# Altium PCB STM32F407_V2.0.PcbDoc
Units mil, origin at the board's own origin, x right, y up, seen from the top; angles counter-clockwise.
Board outline 4845 x 5210 mil, 2 copper layers (Top Layer, Bottom Layer); 115 components, 85 nets, 494 pads, 265 vias.
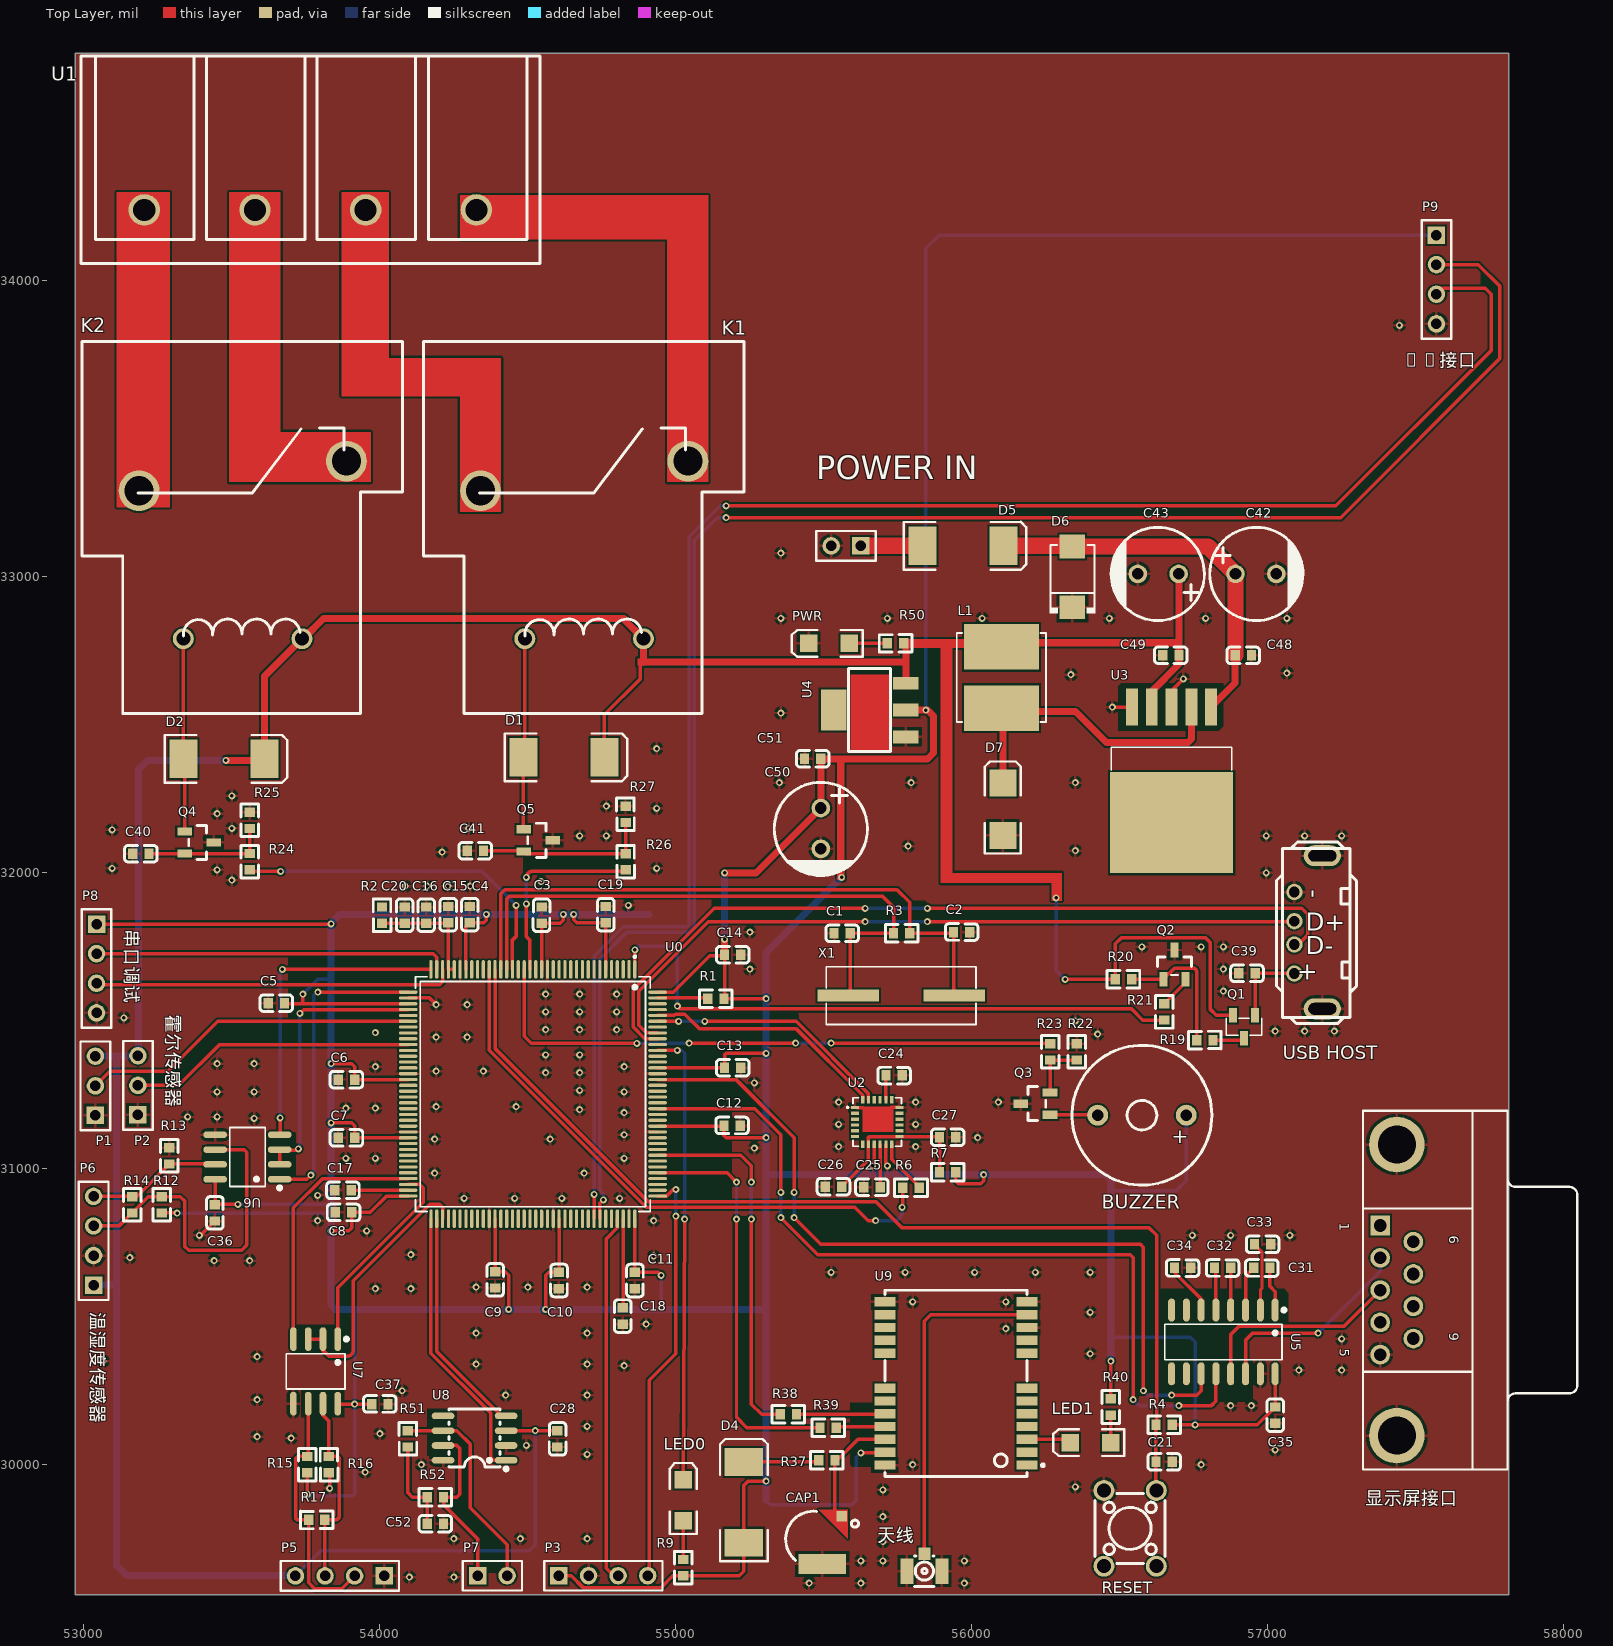
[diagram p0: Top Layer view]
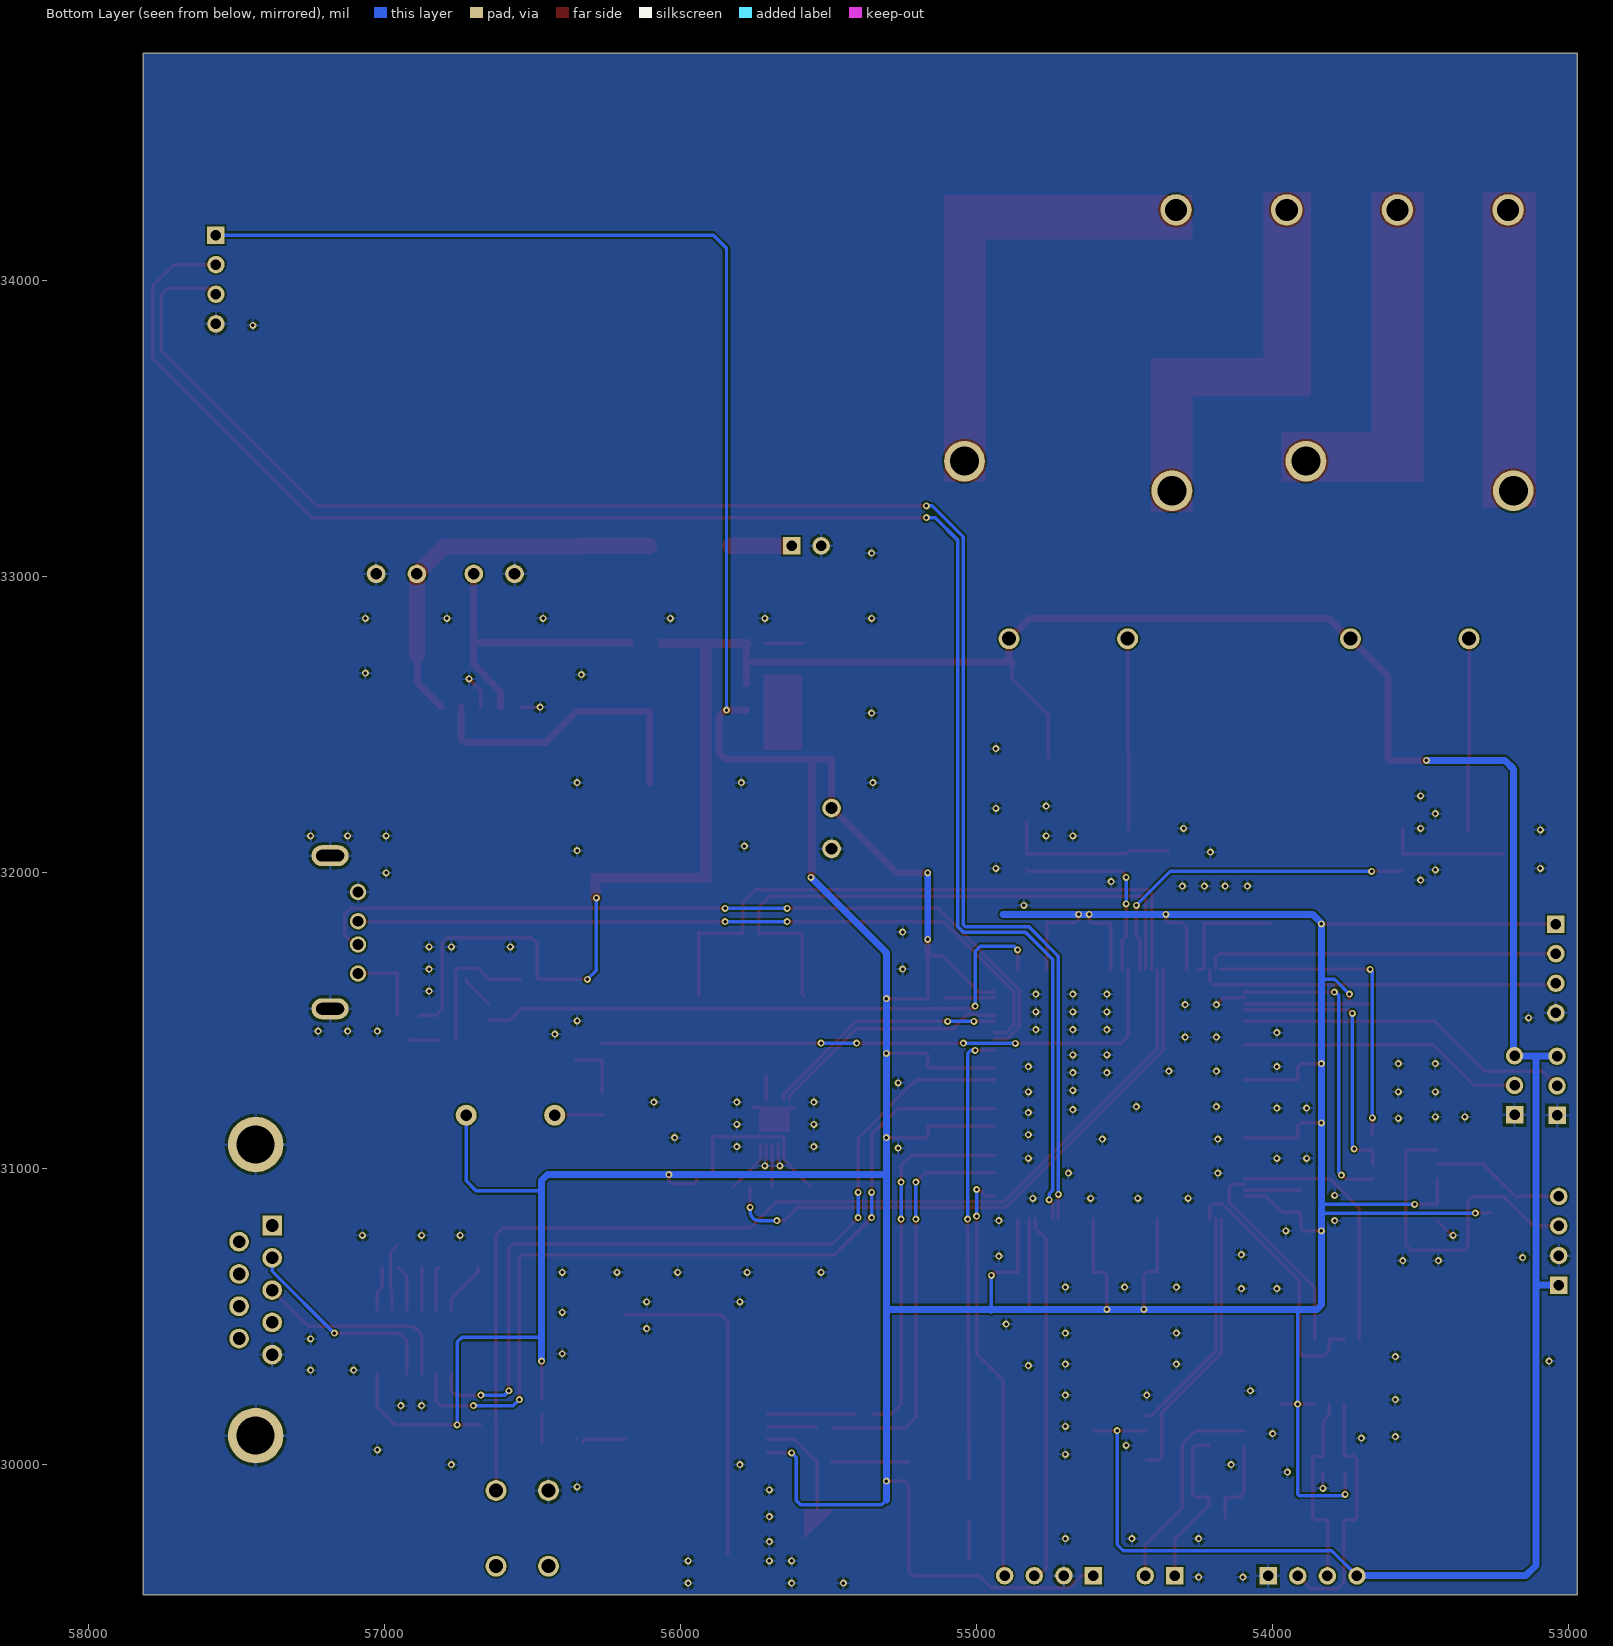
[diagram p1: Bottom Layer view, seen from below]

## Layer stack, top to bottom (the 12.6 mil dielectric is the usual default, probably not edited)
Top Solder: solder mask 0.4, Solder Resist, Dk 3.5
Top Layer: signal copper 1.4
Dielectric 1: dielectric 12.6, FR-4, Dk 4.8
Bottom Layer: signal copper 1.4
Bottom Solder: solder mask 0.4, Solder Resist, Dk 3.5

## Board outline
52970,29560 52970,34770 57815,34770 57815,29560

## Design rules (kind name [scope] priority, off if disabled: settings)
Clearance [All] p1: gap=6
PolygonConnect [All] p1: connectstyle=Relief reliefconductorwidth=10 reliefentries=4 polygonreliefangle="90 Angle" airgapwidth=10
RoutingVias [All] p1: holewidth=11.81 width=23.62 viastyle="Through Hole" minholewidth=11.81 minwidth=23.62 maxholewidth=11.81 maxwidth=23.62
SilkToSolderMaskClearance [IsPad] p1: minsilkscreentomaskgap=0.5 clearancetoexposedcopper=TRUE
SolderMaskExpansion [All] p1: expansion=4
Width [All] p1: maxlimit=78.74 minlimit=9.84 preferedwidth=11.81
Width PWR [InNetClass('PWR')] p2: maxlimit=78.74 minlimit=10 preferedwidth=23.62
29 further rules are at their usual default settings.

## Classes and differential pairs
net class PWR: GND "POWER IN" VCC3.3 VCC5
net class GND: GND

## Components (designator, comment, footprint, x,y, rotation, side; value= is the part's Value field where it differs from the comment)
BUZZER "TMB12A03" BUZ-TH_BD12.0-P7.60-D0.6-FD 56575.1,31181.03 r180 top (schematic designator BUZZER1)
C1 "22nF" SMD_CAP_0603 55562.29,31795.71 r180 top
C2 "22nF" SMD_CAP_0603 55965.83,31799.65 r0 top
C3 "100nF" SMD_CAP_0603 54546.54,31856.73 r90 top
C4 "100nF" SMD_CAP_0603 54304.41,31858.7 r90 top
C5 "100nF" SMD_CAP_0603 53650,31560 r180 top
C6 "100nF" SMD_CAP_0603 53887.08,31301.61 r180 top
C7 "100nF" SMD_CAP_0603 53887.09,31104.76 r180 top
C8 "100nF" SMD_CAP_0603 53877.24,30852.8 r180 top
C9 "100nF" SMD_CAP_0603 54389.06,30624.45 r270 top
C10 "100nF" SMD_CAP_0603 54605,30622.44 r270 top
C11 "100nF" SMD_CAP_0603 54861.5,30622.48 r270 top
C12 "100nF" SMD_CAP_0603 55190.24,31146.1 r0 top
C13 "100nF" SMD_CAP_0603 55192.21,31340.98 r0 top
C14 "100nF" SMD_CAP_0603 55192.21,31722.87 r0 top
C15 "10uF" SMD_CAP_0603 54231.57,31858.7 r90 top
C16 "100nF" SMD_CAP_0603 54156.77,31856.73 r90 top
C17 "225nF" SMD_CAP_0603 53875.28,30927.6 r180 top
C18 "225nF" SMD_CAP_0603 54820.16,30502.4 r270 top
C19 "100nF" SMD_CAP_0603 54763.07,31858.7 r270 top
C20 "225nF" SMD_CAP_0603 54083.94,31856.73 r90 top
C21 "100nF" SMD_CAP_0603 56650,30010 r180 top
C24 "10uF" SMD_CAP_0603 55737.48,31315.39 r180 top
C25 "100nF" SMD_CAP_0603 55662.68,30937.44 r0 top
C26 "10uF" SMD_CAP_0603 55532.76,30939.41 r0 top
C27 "100nF" SMD_CAP_0603 55918.58,31106.73 r180 top
C28 "100nF" SMD_CAP_0603 54600,30087.44 r270 top
C31 "100nF" SMD_CAP_0603 56980,30665 r180 top
C32 "100nF" SMD_CAP_0603 56847.44,30665 r180 top
C33 "100nF" SMD_CAP_0603 56982.56,30745 r180 top
C34 "100nF" SMD_CAP_0603 56712.33,30665 r180 top
C35 "100nF" SMD_CAP_0603 57025,30167.44 r270 top
C36 "100nF/50V" SMD_CAP_0603 53442.2,30850.83 r270 top
C37 "100nF/50V" SMD_CAP_0603 54000,30205 r0 top
C39 "100nF" SMD_CAP_0603 56930,31660 r0 top
C40 "100nF" SMD_CAP_0603 53192.44,32065 r180 top
C41 "100nF" SMD_CAP_0603 54322.44,32075 r180 top
C42 "680uF" CAP-TH_BD8.0-P3.50-D1.0-FD 56960,33010 r0 top
C43 "220uF" CAP-TH_BD8.0-P3.50-D1.0-FD 56630,33010 r180 top
C48 "100nF" SMD_CAP_0603 56917.44,32735 r180 top
C49 "100nF" SMD_CAP_0603 56672.44,32735 r0 top
C50 "220uF" CAP-TH_BD8.0-P3.50-D1.0-FD 55490,32150 r270 top
C51 "100nF" SMD_CAP_0603 55462.44,32385 r0 top
C52 "10nF/50V/10%" SMD_CAP_0603 54187.44,29800 r0 top
CAP1 "70mF" CAP-TH_XH414HG 55555.88,29765.83 r0 top
D1 "Diode" SMC 54621.81,32390 r0 top
D2 "Diode" SMC 53473.19,32385 r0 top
D4 "Diode" SMC 55230,29873.19 r90 top
D5 "Diode" SMC 55970,33105 r0 top
D6 "SMBJ8.0A" SMB_L4.6-W3.6-LS5.3-RD 56340,33000 r90 top
D7 "SK54" SMB 56105,32215 r90 top
K1 "HF105F-1/012D-1HS" RELAY-TH_HF105F-XXX-1HXXX-XXX 54690.39,33090.98 r0 top
K2 "HF105F-1/012D-1HS" RELAY-TH_HF105F-XXX-1HXXX-XXX 53536.69,33090.98 r0 top
L1 "33uH" IND-SMD_L7.0-W6.8 56100,32660 r270 top
LED0 "LED0" 3.2X1.6X1.1 55025,29880 r90 top (schematic designator DS1)
LED1 "LED0" 3.2X1.6X1.1 56401.1,30075 r180 top (schematic designator DS2)
P1 "Hall1" HDR1X3 53038.66,31180.35 r90 top
P2 "Hall2" HDR1X3 53182.36,31181.93 r90 top
P3 "Header 4" HDR1X4 54605,29625 r0 top
P5 "Header 4" HDR1X4 54014.65,29624.45 r180 top
P6 "Header 4" HDR1X4 53032.76,30606.73 r90 top
P7 "Header 2" HDR1X2 54330,29625 r0 top
P8 "Header 4" HDR1X4 53042.6,31826.81 r270 top
P9 "Header 4" HDR1X4 57570,34155 r270 top
"POWER IN" "Header 2" HDR1X2 55625,33105 r180 top (schematic designator P4)
PWR "LED2" 3.2X1.6X1.1 55517.44,32775 r180 top (schematic designator DS3)
Q1 "SI2301" SOT-23-3_L2.9-W1.3-P1.90-LS2.4-BR 56920,31480 r90 top
Q2 "S8050" NUP2105LT1G 56685,31690 r0 top
Q3 "S8050" NUP2105LT1G 56215,31220 r90 top
Q4 "S8050" NUP2105LT1G 53389.2,32102.6 r270 top
Q5 "S8050" NUP2105LT1G 54535,32110 r270 top
R1 "0R" SMD_RES_0603 55135,31575 r180 top
R2 "10R" SMD_RES_0603 54007.17,31856.73 r270 top
R3 "1M" SMD_RES_0603 55763.07,31795.71 r180 top
R4 "10k" SMD_RES_0603 56650,30135 r0 top
R6 "1k" SMD_RES_0603 55794.57,30935.47 r180 top
R7 "10R" SMD_RES_0603 55918.58,30988.62 r180 top
R9 "510R" SMD_RES_0603 55025,29652.44 r270 top
R12 "360R" SMD_RES_0603 53263.07,30878.38 r90 top
R13 "360R" SMD_RES_0603 53288.66,31043.74 r90 top
R14 "120R" SMD_RES_0603 53162.68,30878.38 r270 top
R15 "360R" SMD_RES_0603 53755.2,30000.43 r90 top
R16 "360R" SMD_RES_0603 53828.03,30000.43 r270 top
R17 "120R" SMD_RES_0603 53786.69,29813.43 r180 top
R19 "10k" SMD_RES_0603 56787.44,31435 r0 top
R20 "100k" SMD_RES_0603 56512.44,31640 r180 top
R21 "4.7K" SMD_RES_0603 56650,31530 r270 top
R22 "10K" SMD_RES_0603 56355,31395 r90 top
R23 "1K" SMD_RES_0603 56265,31395 r270 top
R24 "4.7K" SMD_RES_0603 53560,32037.56 r270 top
R25 "47K" SMD_RES_0603 53560,32177.44 r90 top
R26 "4.7K" SMD_RES_0603 54830,32037.44 r270 top
R27 "47K" SMD_RES_0603 54830,32197.44 r90 top
R37 "120R" SMD_RES_0603 55510,30015 r180 top
R38 "510R" SMD_RES_0603 55380,30170 r0 top
R39 "510R" SMD_RES_0603 55515,30125 r0 top
R40 "510R" SMD_RES_0603 56470,30195 r90 top
R50 "2K" SMD_RES_0603 55742.44,32775 r0 top
R51 "60.4R/5%/1/8W" SMD_RES_0603 54095,30087.44 r90 top
R52 "60.4R/5%/1/8W" SMD_RES_0603 54187.44,29890 r0 top
RESET "SW" SW-TH_4P-L6.0-W6.0-P4.50-LS6.5 56535,29785 r270 top (schematic designator SW1)
U0 "STM32F407ZGT6" LQFP-144_L20.0-W20.0-P0.50-LS22.0-BL 54517.01,31252.4 r180 top locked
U1 "DBT50B-9.5-4P" CONN-TH_DBT50B-9.5-4P 53765,34240 r180 top
U2 "MPU6050" QFN-24_L4.0-W4.0-P0.50-BL-EP2.6 55680.39,31157.91 r270 top
U3 "LM2596R-5.0" TO-263-5_L10.2-W8.6-P1.70-LS14.4-TL 56675,32365 r270 top
U4 "AMS1117" SOT-223_L6.7-W3.5-P2.30-BR 55655,32550 r0 top
U5 "MAX3232ID" SOIC-16_L9.9-W3.9-P1.27-LS6.0-BL 56850,30415 r180 top
U6 "SP3485EEN" SOP-8_L5.0-W4.0-P1.27-LS6.0-BL 53552.44,31039.8 r90 top
U7 "SP3485EEN" SOP-8_L5.0-W4.0-P1.27-LS6.0-BL 53782.76,30315.39 r180 top
U8 "TJA1050T/CM,118" SOIC-8_L5.0-W4.0-P1.27-LS6.0-BL 54320,30090 r90 top
U9 "KH-1612-UB8X" GPSM-SMD_KH-1612-UBXX 55946.46,30274.61 r0 top
"USB HOST" "C16722" USB-A-TH_4P-V-F_13.7MM 57137.24,31799.3 r180 top
X1 "8MHz" HC-49S_L11.4-W4.8 55761.1,31585.08 r180 top
天线 "KH-IPEX-K501-29" ANT-SMD_KH-IPEX-K501-29 55840,29670 r0 top (schematic designator RF1)
显示屏接口 "D Connector 9" DSUB1.385-2H9 57810,30590 r270 top (schematic designator J1)

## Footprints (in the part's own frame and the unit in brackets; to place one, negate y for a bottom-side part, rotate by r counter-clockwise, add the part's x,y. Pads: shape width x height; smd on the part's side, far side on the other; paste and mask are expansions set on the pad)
3.2X1.6X1.1 [mm] "SMT LED; 2 Flat Leads"
  rect 1.5x1.5 smd: 1(-1.75,0) 2(1.75,0)
  silkscreen extent -2.9,-1.15 3.2,1.15
ANT-SMD_KH-IPEX-K501-29 [mm]
  rect 1.1x2.2 smd: 1(-1.5,-0.75) 3(1.5,-0.75)
  rect 1x1.05 smd: 2(0,0.75)
  silkscreen extent -0.84,-2.05 0.84,0.55
BUZ-TH_BD12.0-P7.60-D0.6-FD [mm]
  round 1.8 hole 1: 1(-3.8,0) 2(3.8,0)
  silkscreen extent -6,-6 6,6
CAP-TH_BD8.0-P3.50-D1.0-FD [mm]
  round 1.6 hole 1: 1(-1.75,0) 2(1.75,0)
  silkscreen extent -3.96,-4 4.04,4
CAP-TH_XH414HG [mil]
  round 0 smd: 1(-23.48,57.63)
  rect 35x35 smd: 1(5,60)
  rect 161.4x66.93 smd: 2(-60.88,-100.83)
  Top Layer region: -72.69,82.24 25.74,82.24 25.74,-16.19
  silkscreen extent -185,-89 61,77
CONN-TH_DBT50B-9.5-4P [mm]
  round 2.7 hole 1.9: 1(-14.25,0) 2(-4.75,0) 3(4.75,0) 4(14.25,0)
  silkscreen extent -19.7,-13.21 19.7,4.6
DSUB1.385-2H9 [mm] "Connector; D Subminiature; 9 Position; Right Angle; Pitch 1.385 mm"
  rect 1.69x1.69 hole 1.09: 1(-5.54,-10.92)
  round 1.69 hole 1.09: 2(-2.77,-10.92) 3(0,-10.92) 4(2.77,-10.92) 5(5.54,-10.92) 6(-4.155,-8.08) 7(-1.385,-8.08) 8(1.385,-8.08) 9(4.155,-8.08)
  round 4.76 hole 3.26: 10(-12.495,-9.5) 11(12.495,-9.5)
  silkscreen extent -15.4,-12.4 15.4,6
GPSM-SMD_KH-1612-UBXX [mm]
  rect 1.8x0.8 smd: 1(6.1,-7) 2(6.1,-5.9) 3(6.1,-4.8) 4(6.1,-3.7) 5(6.1,-2.6) 6(6.1,-1.5) 7(6.1,-0.4) 8(6.1,2.6) 9(6.1,3.7) 10(6.1,4.8) 11(6.1,5.9) 12(6.1,7) 13(-6.1,7) 14(-6.1,5.9) 15(-6.1,4.8) 16(-6.1,3.7) 17(-6.1,2.6) 18(-6.1,-0.4) 19(-6.1,-1.5) 20(-6.1,-2.6) 21(-6.1,-3.7) 22(-6.1,-4.8) 23(-6.1,-5.9) 24(-6.1,-7)
  silkscreen extent -6.1,-8 7.58,8
HC-49S_L11.4-W4.8 [mm] "晶振8M"
  rect 5.274x1.02 smd: 1(4.553,0) 2(-4.553,0)
  silkscreen extent -6.43,-2.48 6.43,2.48
HDR1X2 [mm] "Connector; Header; 2 Position"
  rect 1.5x1.5 hole 0.9: 1(0,0)
  round 1.5 hole 0.9: 2(2.54,0)
  silkscreen extent -1.27,-1.27 3.81,1.27
HDR1X3 [mm] "Connector; Header; 3 Position"
  rect 1.5x1.5 hole 0.9: 1(0,0)
  round 1.5 hole 0.9: 2(2.54,0) 3(5.08,0)
  silkscreen extent -1.27,-1.27 6.35,1.27
HDR1X4 [mm] "Connector; Header; 4 Position"
  rect 1.5x1.5 hole 0.9: 1(0,0)
  round 1.5 hole 0.9: 2(2.54,0) 3(5.08,0) 4(7.62,0)
  silkscreen extent -1.27,-1.27 8.89,1.27
IND-SMD_L7.0-W6.8 [mm]
  rect 3.924x6.42 smd: 1(2.628,0) 2(-2.628,0)
  silkscreen extent -3.83,-3.83 3.83,3.83
LQFP-144_L20.0-W20.0-P0.50-LS22.0-BL [mm] "MCU"
  oval 0.28x1.6 smd: 1(-8.75,-10.7) 2(-8.25,-10.7) 3(-7.75,-10.7) 4(-7.25,-10.7) 5(-6.75,-10.7) 6(-6.25,-10.7) 7(-5.75,-10.7) 8(-5.25,-10.7) 9(-4.75,-10.7) 10(-4.25,-10.7) 11(-3.75,-10.7) 12(-3.25,-10.7) 13(-2.75,-10.7) 14(-2.25,-10.7) 15(-1.75,-10.7) 16(-1.25,-10.7) 17(-0.75,-10.7) 18(-0.25,-10.7) 19(0.25,-10.7) 20(0.75,-10.7) 21(1.25,-10.7) 22(1.75,-10.7) 23(2.25,-10.7) 24(2.75,-10.7) 25(3.25,-10.7) 26(3.75,-10.7) 27(4.25,-10.7) 28(4.75,-10.7) 29(5.25,-10.7) 30(5.75,-10.7) 31(6.25,-10.7) 32(6.75,-10.7) 33(7.25,-10.7) 34(7.75,-10.7) 35(8.25,-10.7) 36(8.75,-10.7) 73(8.75,10.7) 74(8.25,10.7) 75(7.75,10.7) 76(7.25,10.7) 77(6.75,10.7) 78(6.25,10.7) 79(5.75,10.7) 80(5.25,10.7) 81(4.75,10.7) 82(4.25,10.7) 83(3.75,10.7) 84(3.25,10.7) 85(2.75,10.7) 86(2.25,10.7) 87(1.75,10.7) 88(1.25,10.7) 89(0.75,10.7) 90(0.25,10.7) 91(-0.25,10.7) 92(-0.75,10.7) 93(-1.25,10.7) 94(-1.75,10.7) 95(-2.25,10.7) 96(-2.75,10.7) 97(-3.25,10.7) 98(-3.75,10.7) 99(-4.25,10.7) 100(-4.75,10.7) 101(-5.25,10.7) 102(-5.75,10.7) 103(-6.25,10.7) 104(-6.75,10.7) 105(-7.25,10.7) 106(-7.75,10.7) 107(-8.25,10.7) 108(-8.75,10.7)
  oval 1.6x0.28 smd: 37(10.7,-8.75) 38(10.7,-8.25) 39(10.7,-7.75) 40(10.7,-7.25) 41(10.7,-6.75) 42(10.7,-6.25) 43(10.7,-5.75) 44(10.7,-5.25) 45(10.7,-4.75) 46(10.7,-4.25) 47(10.7,-3.75) 48(10.7,-3.25) 49(10.7,-2.75) 50(10.7,-2.25) 51(10.7,-1.75) 52(10.7,-1.25) 53(10.7,-0.75) 54(10.7,-0.25) 55(10.7,0.25) 56(10.7,0.75) 57(10.7,1.25) 58(10.7,1.75) 59(10.7,2.25) 60(10.7,2.75) 61(10.7,3.25) 62(10.7,3.75) 63(10.7,4.25) 64(10.7,4.75) 65(10.7,5.25) 66(10.7,5.75) 67(10.7,6.25) 68(10.7,6.75) 69(10.7,7.25) 70(10.7,7.75) 71(10.7,8.25) 72(10.7,8.75) 109(-10.7,8.75) 110(-10.7,8.25) 111(-10.7,7.75) 112(-10.7,7.25) 113(-10.7,6.75) 114(-10.7,6.25) 115(-10.7,5.75) 116(-10.7,5.25) 117(-10.7,4.75) 118(-10.7,4.25) 119(-10.7,3.75) 120(-10.7,3.25) 121(-10.7,2.75) 122(-10.7,2.25) 123(-10.7,1.75) 124(-10.7,1.25) 125(-10.7,0.75) 126(-10.7,0.25) 127(-10.7,-0.25) 128(-10.7,-0.75) 129(-10.7,-1.25) 130(-10.7,-1.75) 131(-10.7,-2.25) 132(-10.7,-2.75) 133(-10.7,-3.25) 134(-10.7,-3.75) 135(-10.7,-4.25) 136(-10.7,-4.75) 137(-10.7,-5.25) 138(-10.7,-5.75) 139(-10.7,-6.25) 140(-10.7,-6.75) 141(-10.7,-7.25) 142(-10.7,-7.75) 143(-10.7,-8.25) 144(-10.7,-8.75)
  silkscreen extent -10.08,-11.9 10.08,10.08
NUP2105LT1G [mm]
  rect 0.7x1.25 smd: 1(-0.95,-1.25) 2(0.95,-1.25) 3(0,1.25)
  silkscreen extent -1.46,-0.9 1.46,0.65
QFN-24_L4.0-W4.0-P0.50-BL-EP2.6 [mm]
  rect 0.28x0.665 smd: 1(-1.25,-1.907) 2(-0.75,-1.907) 3(-0.25,-1.907) 4(0.25,-1.907) 5(0.75,-1.907) 6(1.25,-1.907) 13(1.25,1.907) 14(0.75,1.907) 15(0.25,1.907) 16(-0.25,1.907) 17(-0.75,1.907) 18(-1.25,1.907)
  rect 0.665x0.28 smd: 7(1.907,-1.25) 8(1.907,-0.75) 9(1.907,-0.25) 10(1.907,0.25) 11(1.907,0.75) 12(1.907,1.25) 19(-1.907,1.25) 20(-1.907,0.75) 21(-1.907,0.25) 22(-1.907,-0.25) 23(-1.907,-0.75) 24(-1.907,-1.25)
  silkscreen extent -2.08,-2.61 2.08,2.08
RELAY-TH_HF105F-XXX-1HXXX-XXX [mm]
  round 3.5 hole 2.5: 2(8.9,7.62) 5(-8.9,5.08)
  round 1.8 hole 1.2: 3(5.08,-7.62) 4(-5.1,-7.62)
  silkscreen extent -13.8,-14.02 13.7,17.88
SMB [mm] "DO-214-AA/SMB; 2 C-Bend Leads; Body 5.3 x 3.6 mm, inc. leads (LxW)"
  rect 2.3x2.3 smd: 1(-2.25,0) 2(2.25,0)
  silkscreen extent -3.8,-1.55 4.1,1.55
SMB_L4.6-W3.6-LS5.3-RD [mil]
  rect 80.61x86.31 smd: 1(-102.71,0) 2(102.71,0)
  silkscreen extent -123,-77 108,77
SMC [mm] "DO-214-AB/SMC; 2 C-Bend Leads; Body 7.9 x 5.9 mm, inc. leads (LxW)"
  rect 2.4x3.3 smd: 1(-3.475,0) 2(3.475,0)
  silkscreen extent -5.07,-2.05 5.43,2.05
SMD_CAP_0603 [mm]
  rect 0.8x0.9 smd: 1(-0.7,0) 2(0.7,0)
  silkscreen extent -1.4,-0.7 1.4,0.72
SMD_RES_0603 [mm]
  rect 0.8x0.9 smd: 1(-0.7,0) 2(0.7,0)
  silkscreen extent -1.4,-0.75 1.4,0.76
SOIC-8_L5.0-W4.0-P1.27-LS6.0-BL [mil]
  oval 22.38x76.78 smd: 1(-75,-106.5) 2(-25,-106.5) 3(25,-106.5) 4(75,-106.5) 5(75,106.5) 6(25,106.5) 7(-25,106.5) 8(-75,106.5)
  silkscreen extent -110,-112 98,87
SOIC-16_L9.9-W3.9-P1.27-LS6.0-BL [mil]
  oval 23.7x77.6 smd: 1(-175,-107.7) 2(-125,-107.7) 3(-75,-107.7) 4(-25,-107.7) 5(25,-107.7) 6(75,-107.7) 7(125,-107.7) 8(175,-107.7) 9(175,107.7) 10(125,107.7) 11(75,107.7) 12(25,107.7) 13(-25,107.7) 14(-75,107.7) 15(-125,107.7) 16(-175,107.7)
  silkscreen extent -211,-114 198,60
SOP-8_L5.0-W4.0-P1.27-LS6.0-BL [mil]
  oval 22.6x80.14 smd: 1(-75,-108.97) 2(-25,-108.97) 3(25,-108.97) 4(75,-108.97) 5(75,108.97) 6(25,108.97) 7(-25,108.97) 8(-75,108.97)
  silkscreen extent -110,-115 99,60
SOT-23-3_L2.9-W1.3-P1.90-LS2.4-BR [mm]
  rect 1.25x0.7 smd: 1(1,-0.95) 2(1,0.95) 3(-1,0)
  silkscreen extent -0.73,-1.53 0.73,1.53
SOT-223_L6.7-W3.5-P2.30-BR [mm]
  rect 2.2x1.1 smd: 1(3.099,-2.3) 2(3.099,0) 3(3.099,2.3)
  rect 2.2x3.5 smd: 4(-3.099,0)
  silkscreen extent -1.8,-3.55 1.8,3.55
SW-TH_4P-L6.0-W6.0-P4.50-LS6.5 [mm]
  round 1.8 hole 1.2: 1(-3.25,2.25) 2(3.25,2.25) 3(-3.25,-2.25) 4(3.25,-2.25)
  silkscreen extent -3,-3 3,3
TO-263-5_L10.2-W8.6-P1.70-LS14.4-TL [mm]
  rect 3.183x1.02 smd: 1(-4.953,3.4) 2(-4.953,1.7) 3(-4.953,0) 4(-4.953,-1.7) 5(-4.953,-3.4)
  rect 8.705x10.587 smd: 6(4.953,0)
  silkscreen extent -1.52,-5.17 0.45,5.17
USB-A-TH_4P-V-F_13.7MM [mm]
  round 1.4 hole 0.92: 1(1.2,3.551) 2(1.2,1.052) 3(1.2,-0.947) 4(1.2,-3.447)
  oval 3.2x1.8 hole 1 slot 2.4 at 0 deg: 5(-1.2,-6.571) 6(-1.2,6.571)
  silkscreen extent -4.12,-7.74 2.74,7.83

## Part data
BUZZER: "蜂鸣器"
C1 C2 C3 C4 C5 C6 C7 C8 C9 C10 C11 C12 C13 C14 C15 C16 C17 C18 C21 C24 C25 C26 C27 C28 C31 C32 C33 C34 C35 C36 C37 C39 C40 C41 C52: library part Cap, "Capacitor"
C19 C20: library part Cap, "陶瓷电容"
CAP1: library part "Super Cap"
D1 D2 D4 D5: "Default Diode"
D6: library part SMBJ8.0A_C726816
D7: library part "D Schottky", "Schottky Diode"
K1 K2: "继电器"
LED0 LED1: library part LED2, "Typical RED, GREEN, YELLOW, AMBER GaAs LED"
P1 P2: library part "Header 3", "Header, 3-Pin"
P3 P5 P6 P8 P9: "Header, 4-Pin"
P7 "POWER IN": "Header, 2-Pin"
PWR: "Typical RED, GREEN, YELLOW, AMBER GaAs LED"
Q1: library part SI2301_C427391
Q2 Q3 Q4 Q5: library part NPN, "NPN Bipolar Transistor"
R1 R2 R3 R4 R6 R7: library part Res1, "Resistor"
R9 R40 R50: library part Res1, "水泥电阻"
R12 R13 R14 R15 R16 R17 R19 R20 R21 R22 R23 R24 R25 R26 R27 R37 R38 R39 R51 R52: library part "Res Semi", "Semiconductor Resistor"
U0: "MCU"
U1: "接线端子"
U2: library part MPU-6050_C24112, "陀螺仪"
U4: library part ASM1117
U9: "GPS"
"USB HOST": "USB_HOST"
X1: "贴片晶振"
天线: "天线插座"
显示屏接口: "Receptacle Assembly, 9 Position, Right Angle"

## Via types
v1: diameter 23.62, hole 11.81, Top Layer to Bottom Layer, tented both sides, 265 vias

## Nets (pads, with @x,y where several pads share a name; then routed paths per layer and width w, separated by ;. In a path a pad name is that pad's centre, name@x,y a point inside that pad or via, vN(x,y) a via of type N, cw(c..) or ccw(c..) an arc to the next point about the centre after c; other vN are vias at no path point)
"3D INT": R6.2 U0.26 | length 2005.3
  Top Layer w11.81: U0.26 54369.37,31401.01 54900.38,30870 55605,30870 55650,30825 v1(55675,30825) ; v1(55765,30870) 55767.01,30872.01 R6.2
  Bottom Layer w11.81: v1(55675,30825) 55735,30825 ccw(c55735,30855) 55765,30855 v1(55765,30870)
"A CAM": P5.2 R15.2 R17.2 U7.6 | length 864.1
  Top Layer w11.81: U7.6 53757.76,30030.55 R15.2 53722.99,30027.99 53715,30020 53715,29820 53721.57,29813.43 R17.2 53759.13,29600.87 53778.98,29581.02 53871.21,29581.02 P5.2
"A TEMP": P6.3 R12.2 R14.2 U6.6 | length 1155.4
  Top Layer w11.81: P6.3 53118.58,30806.73 R14.2 53217.79,30905.94 R12.2 53326.07,30905.94 53339.84,30892.17 53339.84,30738.62 53353.62,30724.84 53532.76,30724.84 53550.47,30742.56 53550.47,31055.55 53542.01,31064.02 53542.01,31064.8 U6.6
"B CAM": P5.3 R16.1 R17.1 U7.7 | length 665.5
  Top Layer w11.81: U7.7 53807.76,30167.24 53828.03,30146.97 R16.1 53857.01,30027.99 53863.43,30021.57 53863.43,29823.43 53853.43,29813.43 R17.1 53814.25,29624.84 P5.3
"B TEMP": P6.4 R13.1 R14.1 U6.7 | length 457.3
  Top Layer w11.81: P6.4 53161.89,30906.73 R14.1 53178.42,30905.94 R13.1 53442.1,31016.18 U6.7
BEEP: R23.1 U0.20 | length 2014.4
  Top Layer w11.81: U0.20 54487.48,31447.52 54511.28,31423.72 v1(54868.72,31423.72) ; v1(55045,31425) v1(55405,31425) ; v1(55525,31425) 56262.56,31425 R23.1
  Bottom Layer w11.81: v1(54868.72,31423.72) v1@55044.82,31423.72 ; v1(55405,31425) v1(55525,31425)
"CAN RX": U0.74 U8.4 | length 772.7
  Top Layer w11.81: U0.74@54192.47,30831.14 54192.47,30382.72 54332.81,30242.38 54332.81,30242.19 54410,30165 U8.4
"CAN TX": U0.73 U8.1 | length 945.7
  Top Layer w11.81: U0.73 54172.52,30377.29 54375,30174.81 54375,30025 54385,30015 U8.1
CANH: P7.1 R52.2 U8.7 | length 587.4
  Top Layer w11.81: U8.7 54260,30065 54270,30055 54270,29900 54260,29890 R52.2 54215,29865 54330,29750 P7.1
CANL: P7.2 R51.2 U8.6 | length 725.4
  Top Layer w11.81: R51.2 U8.6 54260,30115 54305,30070 54305,29855 54430,29730 P7.2
GND: "POWER IN.2" "USB HOST.4" "USB HOST.5" "USB HOST.6" C1.2 C2.2 C3.2 C4.2 C5.2 C6.2 C7.2 C8.2 C9.2 C10.2 C11.2 C12.2 C13.2 C14.2 C15.2 C16.2 C17.2 C18.2 C19.1 C20.2 C21.1 C24.1 C25.1 C26.1 C27.1 C28.2 C33.1 C34.1 C35.2 C36.2 C37.2 C39.1 C40.2 C41.2 C42.2 C43.2 C48.1 C49.1 C50.2 C51.1 C52.2 CAP1.2 D6.1 D7.1 P1.1 P2.1 P3.2 P5.1 P6.2 P8.4 P9.4 PWR.2 Q2.3 Q3.3 Q4.3 Q5.3 R13.2 R16.2 R22.2 R25.2 R27.2 RESET.3 U0.16 U0.31 U0.38 U0.51 U0.61 U0.83 U0.94 U0.107 U0.120 U0.130 U2.1 U2.9 U2.11 U2.18 U3.3 U3.5 U4.1 U5.15 U6.5 U7.5 U8.2 U8.8 U9.10 U9.12 U9.13 U9.24 天线.1 天线.3 显示屏接口.5 显示屏接口.10 显示屏接口.11 | length 585.4
  Top Layer w11.81: v1(53390,30775) 53393.93,30775 C36.2 ; R16.2 53830,29970.91 v1(53830,29920) ; U0.38 54167.8,31577.2 v1(54190,31555) ; v1(55665,31010) 55670.55,31015.55 U2.9 ; U2.11 55709.92,31015.08 v1(55715,31010) ; 55727.13,31207.13 U2.18 ; v1(56475,32560) U3.5 ; U3.3 56675,32615 v1(56715,32655)
  other v1: 55450,29600 55625,29600 55975,29600 54100,29620 54250,29620 55625,29675 55700,29675 55975,29675 55700,29740 54250,29750 54475,29750 54700,29750 55700,29825 55700,29915 56350,29925 53950,29975 54140,30000 55800,30000 56775,30000 54700,30035 57025,30050 54495,30065 53700,30090 53585,30095 54000,30105 54700,30130 56875,30200 56945,30200 53585,30220 54425,30235 54700,30235 54075,30250 57105,30320 57250,30320 54825,30335 54325,30340 54700,30340 53065,30350 53585,30365 56400,30375 57250,30425 54325,30445 54700,30445 56115,30460 54900,30475 56400,30515 55800,30550 56115,30550 53985,30595 54105,30595 54325,30600 54500,30600 54700,30600 55525,30650 55775,30650 56010,30650 56215,30650 56400,30650 53440,30690 53560,30690 53155,30700 54925,30705 54105,30710 56745,30775 56875,30775 57075,30775 53955,30790 53790,30825 54925,30825 54285,30900 54455,30900 54615,30900 54810,30900 53790,30910 54185,30985 54690,30985 53885,31035 53985,31035 54825,31035 55265,31070 55550,31075 55810,31075 54185,31100 54575,31100 56020,31105 54825,31115 55550,31150 55810,31150 53575,31170 53350,31175 53450,31175 54825,31190 54675,31200 53885,31205 53985,31205 54190,31210 54460,31210 55550,31225 55810,31225 56090,31225 53450,31260 53575,31260 54825,31260 54675,31265 55265,31290 54560,31325 54675,31325 54190,31330 54350,31330 53985,31345 54825,31345 53450,31355 53575,31355 54560,31385 54675,31385 54190,31445 54295,31445 56425,31455 53985,31460 57025,31465 57125,31465 57225,31465 54560,31470 54675,31470 54800,31470 56350,31500 53135,31510 54560,31530 54675,31530 54800,31530 54295,31555 54560,31590 54675,31590 54800,31590 56850,31600 55250,31675 56850,31675 56575,31750 56775,31750 56850,31750 55250,31800 54840,31890 54085,31955 54160,31955 54230,31955 54305,31955 54545,31970 53500,31975 56995,32000 53450,32010 53095,32015 54935,32015 54210,32070 56350,32075 55785,32090 54675,32125 54765,32125 56995,32125 57125,32125 57250,32125 53095,32145 53500,32150 54300,32150 53450,32200 54935,32217.5 54765,32225 53500,32260 55350,32305 55795,32305 56350,32305 54935,32420 55355,32540 56335,32670 57065,32675 55355,32860 55715,32860 56035,32860 56465,32860 56790,32860 57065,32860 55355,33080 57445,33850
HALL1: P1.2 U0.42 | length 1147.4
  Top Layer w11.81: P1.2 53087.48,31329.17 53282.76,31329.17 53452.05,31498.46 U0.42
HALL2: P2.2 U0.46 | length 970.5
  Top Layer w11.81: P2.2 53320.16,31281.93 53457.95,31419.72 U0.46
"IIC SCL": U0.139 U2.23 | length 834.9
  Top Layer w11.81: U0.139 v1(55009.13,31498.46) ; v1(55097.72,31498.46) 55406.54,31498.46 55650.87,31254.13 U2.23
  Bottom Layer w11.81: v1(55009.13,31498.46) v1(55097.72,31498.46)
"IIC SDA": U0.140 U2.24 | length 823.5
  Top Layer w11.81: U0.140 54995.28,31518.15 54999.31,31522.18 55030.69,31522.18 55078.94,31473.94 55405.87,31473.94 55631.18,31248.63 U2.24
LED0: LED0.2 U0.134 | length 1535.9
  Top Layer w11.81: U0.134 U0.134 v1(55005,31400) ; LED0.2@55025,29950 v1(55030,30830)
  Bottom Layer w11.81: v1(55005,31400) 55020,31400 55030,31390 v1(55030,30830)
NetBUZZER1_2: BUZZER.2 Q3.1 | length 161.9
  Top Layer w11.81: Q3.1 56423.92,31182.6 BUZZER.2
NetC1_1: C1.1 R3.2 U0.23 X1.1 | length 2013
  Top Layer w11.81: U0.23 54428.42,31911.85 54438.27,31921.69 55698.11,31921.69 55735.51,31884.29 R3.2 C1.1 55589.84,31593.07 X1.1
NetC2_1: C2.1 R3.1 U0.24 X1.2 | length 2130.6
  Top Layer w11.81: U0.24 54408.74,31929.85 54422.24,31943.35 55747.32,31943.35 55790.63,31900.04 R3.1 55934.33,31795.71 C2.1 55938.27,31587.16 X1.2
NetC15_1: C15.1 C16.1 C20.1 R2.2 U0.32 U0.33 | length 402.4
  Top Layer w11.81: R2.2 C20.1 ; C20.1 C16.1 ; C16.1 54229.61,31829.18 C15.1 U0.33 U0.32
NetC17_1: C17.1 U0.71 | length 192.9
  Top Layer w11.81: C17.1 U0.71
NetC18_1: C18.1 U0.106 | length 302
  Top Layer w11.81: C18.1 54822.13,30531.93 U0.106
NetC24_2: C24.2 U2.20 | length 82.4
  Top Layer w11.81: U2.20 C24.2
NetC25_2: C25.2 U2.10 | length 145.4
  Top Layer w11.81: C25.2 U2.10
NetC26_2: C26.2 C27.2 R7.2 U2.8 U2.13 | length 564.7
  Top Layer w11.81: C26.2 55650.87,31029.96 U2.8 55650.87,31106.73 55652.83,31108.7 U2.13 55889.06,31108.7 C27.2 R7.2
NetC31_1: C31.1 U5.1 | length 149.5
  Top Layer w11.81: C31.1 57007.56,30602.44 57025,30585 U5.1
NetC31_2: C31.2 U5.3 | length 153.7
  Top Layer w11.81: U5.3 56925,30637.56 C31.2
NetC32_1: C32.1 U5.4 | length 142.3
  Top Layer w11.81: U5.4 C32.1
NetC32_2: C32.2 U5.5 | length 144.4
  Top Layer w11.81: C32.2 56825,30659.89 U5.5
NetC33_2: C33.2 U5.2 | length 234.7
  Top Layer w9.84: C33.2 56980,30720 56980,30595 56975,30590 U5.2
NetC34_2: C34.2 U5.6 | length 179.7
  Top Layer w11.81: C34.2 56684.77,30650.23 56775,30560 U5.6
NetC39_2: "USB HOST.1" C39.2 Q1.1 | length 273.3
  Top Layer w11.81: Q1.1 56957.56,31519.52 C39.2 57089.5,31660 57090,31659.5
NetC40_1: C40.1 Q4.2 R24.1 R25.1 | length 424.9
  Top Layer w11.81: C40.1 53339.8,32065 Q4.2 53559.92,32065.2 R24.1 R25.1
NetC41_1: C41.1 Q5.2 R26.1 R27.1 | length 589
  Top Layer w11.81: C41.1 54483.4,32075 Q5.2 54493.4,32065 R26.1 R27.1
NetC42_1: C42.1 C48.2 D5.2 D6.2 U3.1 | length 1352.2
  Top Layer w11.81: 56290,33102.71 D6.2@56337.71,33105 ; C48.2 C48.2@56891.1,32736.21
  Top Layer w23.62: U3.1 56889.89,32641.03 C48.2
  Top Layer w55.12: D5.2 D6.2@56337.71,33105 ; D6.2 56798.39,33102.71 C42.1 C48.2@56891.1,32736.21
NetC52_1: C52.1 R51.1 R52.1 | length 295.9
  Top Layer w11.81: R51.1 54095,29905 54110,29890 R52.1 54159.88,29820.12
NetCAP1_1: CAP1.1 R37.1 U9.22 | length 391.7
  Top Layer w11.81: 55532.4,29823.47 55537.56,29828.62 R37.1 55545,30015 55615.63,30085.63 U9.22
NetD1_1: D1.1 K1.4 Q5.1 | length 648.7
  Top Layer w11.81: Q5.1 54485,32148.2 D1.1 54481.57,32393.43 54489.6,32401.46 K1.4
NetD2_1: D2.1 K2.4 Q4.1 | length 652.7
  Top Layer w11.81: K2.4 53335.91,32385.47 D2.1 53340,32381.38 Q4.1
NetD4_2: D4.2 R37.2 | length 260
  Top Layer w11.81: D4.2 R37.2@55490,30010
NetD7_2: D7.2 L1.1 U3.2 | length 1037
  Top Layer w11.81: L1.1@56105,32546.53 L1.1@56106.54,32545
  Top Layer w23.62: D7.2 L1.1@56105,32546.53 ; L1.1@56106.54,32545 56350,32545 56455,32440 56730,32440 56741.93,32451.93 U3.2
NetDS1_1: LED0.1 R9.1 | length 131.1
  Top Layer w11.81: R9.1 LED0.1
NetDS2_1: LED1.1 R40.1 | length 92.5
  Top Layer w11.81: LED1.1 56469.88,30075.12 56470,30075.23 R40.1
NetDS3_1: PWR.1 R50.1 | length 128.5
  Top Layer w11.81: PWR.1 R50.1
NetJ1_2: U5.14 显示屏接口.2 | length 709.8
  Top Layer w11.81: U5.14 56925,30420 56950,30445 v1(57170,30445)
  Bottom Layer w11.81: v1(57170,30445) 57171.19,30445 57380.08,30653.88 显示屏接口.2
NetJ1_3: U5.13 显示屏接口.3 | length 699.9
  Top Layer w11.81: U5.13 56875,30440 56903.72,30468.72 57258.8,30468.72 显示屏接口.3
NetK1_2: K1.2 U1.1
NetK1_5: K1.5 U1.2
NetK2_2: K2.2 U1.3
NetK2_5: K2.5 U1.4
NetQ1_3: Q1.3 R19.2 | length 107.3
  Top Layer w11.81: R19.2 56914.37,31435 Q1.3
NetQ2_1: Q2.1 R19.1 R20.1 | length 473.3
  Top Layer w11.81: R20.1 56646.8,31640 Q2.1 56685,31678.2 56746.8,31678.2 cw(c56746.8,31665.12) 56759.88,31665.12 R19.1
NetQ2_2: Q2.2 R21.1 | length 113.2
  Top Layer w11.81: R21.1 56722.4,31629.96 Q2.2
NetQ3_2: Q3.2 R22.1 R23.2 | length 200.4
  Top Layer w11.81: Q3.2 56265,31258.2 R23.2 R22.1
NetR1_2: R1.2 U0.143 | length 170.1
  Top Layer w11.81: U0.143 55105.24,31577.2 R1.2
NetR6_1: R6.1 U2.12 | length 185.7
  Top Layer w11.81: U2.12 55729.61,31031.93 55822.13,30939.41 R6.1
NetR38_2: R38.2 U9.20 | length 299.7
  Top Layer w11.81: R38.2 55704.06,30170 U9.20
NetR39_2: R39.2 U9.21 | length 165.4
  Top Layer w11.81: R39.2 55546.5,30128.94 U9.21
NetRF1_2: U9.11 天线.2 | length 1141.2
  Top Layer w11.81: 天线.2 55840,30485 55861.89,30506.89 U9.11
NRST: C21.2 R4.1 RESET.1 U0.25 | length 3628.3
  Top Layer w11.81: U0.25 54389.05,31406.51 54907.75,30887.81 55677.19,30887.81 55765,30800 56600,30800 56625,30775 56625,30137.56 R4.1 C21.2 56622.44,29914.09 RESET.1
"POWER IN": "POWER IN.1" D5.1 | length 208.2
  Top Layer w55.12: 55625,33105 D5.1
PPS: LED1.2 U9.3 | length 150.9
  Top Layer w11.81: U9.3 56321.57,30085.63 LED1.2 ; LED1.2@56351.57,30085.63 LED1.2@56352.2,30085
"RE CAM": U0.75 U7.2 U7.3 | length 897
  Top Layer w11.81: U7.3 U7.2 53807.76,30386.23 53829.52,30365.75 53890,30365.75 ccw(c53887.88,30387.88) 53910,30390 53910,30622.07 54167.93,30880 54201.54,30880 54211.89,30869.65 U0.75
"RE TEMP": U0.40 U6.2 U6.3 | length 942.1
  Top Layer w11.81: U6.2 U6.3 53662.79,31063.43 v1@53721.73,31063.43 ; v1(53730,31525) 53742.83,31537.83 U0.40
  Bottom Layer w11.81: v1(53724.61,31067.05) 53730,31072.44 v1(53730,31525)
RELAY1: R26.2 U0.19 | length 664.8
  Top Layer w11.81: v1(54495,31895) 54495,31785 54507.16,31772.84 U0.19 ; v1(54495,31985) cw(c54515,31985) 54515,32005 54825.12,32005 R26.2
  Bottom Layer w11.81: v1(54495,31895) v1(54495,31985)
RELAY2: R24.2 U0.22 | length 1171
  Top Layer w11.81: R24.2 53565,32005 v1(53665,32005) ; U0.22 54448.11,31773.11 54460,31785 v1(54460,31890)
  Bottom Layer w11.81: v1(53665,32005) 54345,32005 v1(54460,31890)
SWCLK: P3.4 U0.109 | length 1439.4
  Top Layer w11.81: P3.4 54925,29625 54910,29640 54910,30285 55000,30375 v1(55000,30840) ; U0.109 54969.2,30907.91 54991.28,30930 v1(55000,30930)
  Bottom Layer w11.81: v1(55000,30840) v1(55000,30930)
SWDIO: P3.3 U0.105 | length 1247
  Top Layer w11.81: U0.105 54802.44,30800.21 54765,30762.77 54765,29650 54790,29625 P3.3
"U1 RX": P9.2 U0.102 | length 6020.9
  Top Layer w11.81: U0.102 54743.39,30883.39 v1(54755,30895) ; v1(55170,33200) 57246.57,33200 57783.28,33736.72 57783.28,33983.28 57711.57,34055 P9.2
  Bottom Layer w11.81: v1(54755,30895) 54755,30915.94 54743.39,30927.56 54743.39,31708.39 54835,31800 55045,31800 55062.81,31817.81 55062.81,33122.81 55140,33200 v1(55170,33200)
"U1 TX": P9.3 U0.101 | length 5925.3
  Top Layer w11.81: U0.101 v1(54723.7,30913.7) ; v1(55170,33240) 57230,33240 57755,33765 57755,33955 57735,33975 57590,33975 P9.3
  Bottom Layer w11.81: v1(54723.7,30913.7) 54723.7,31718.7 54822.81,31817.81 55037.62,31817.81 55045,31825.19 55045,33135 55150,33240 v1(55170,33240)
"U2 RX": U0.37 U6.1 | length 1049
  Top Layer w11.81: U6.1 53753.03,30964.8 v1(53767.01,30978.78) ; v1(53790.63,31596.89) 53866.91,31596.89 54019.47,31596.89 U0.37
  Bottom Layer w11.81: v1(53767.01,30978.78) 53776.85,30988.62 53776.85,31587.05 53782.76,31592.95 53790.63,31592.95 v1(53790.63,31596.89)
"U2 TX": U0.36 U6.4 | length 1064.6
  Top Layer w11.81: U6.4 53662.68,31116.07 v1(53662.68,31171.69) ; v1(53670.55,31673.66) U0.36
  Bottom Layer w11.81: v1(53662.68,31171.69) 53662.68,31665.79 v1(53670.55,31673.66)
"U3 RX": U0.70 U7.1 | length 687
  Top Layer w11.81: U7.1 53857.76,30597.84 54146.93,30887.01 54146.93,30935.47 54135.12,30947.28 U0.70
"U3 TX": U0.69 U7.4 | length 872.8
  Top Layer w11.81: U7.4 53707.76,30868.35 53806.38,30966.97 U0.69
"U4 RX": P8.2 U0.35 | length 1195.8
  Top Layer w11.81: P8.2 54180.39,31726.81 54192.2,31715 U0.35
"U4 TX": P8.3 U0.34 | length 1216.5
  Top Layer w11.81: P8.3 53046.93,31622.48 54202.05,31622.48 54211.89,31632.32 U0.34
"U5 RX": R38.1 U0.116 | length 1248.5
  Top Layer w11.81: U0.116 55219.29,31045.71 55255,31010 v1(55255,30955) ; v1(55255,30830) 55255,30205 55290,30170 R38.1
  Bottom Layer w11.81: v1(55255,30830) v1(55255,30955)
"U5 TX": R39.1 U0.113 | length 1371.8
  Top Layer w11.81: U0.113 55173.35,30986.65 v1(55205,30955) ; v1(55205,30830) 55205,30160 55240,30125 R39.1
  Bottom Layer w11.81: v1(55205,30830) v1(55205,30955)
"U6 RX": U0.124 U5.12 | length 2846
  Top Layer w11.81: U0.124 55266.81,31203.19 55355,31115 v1(55355,30920) ; v1(55355,30835) 55480,30710 56535,30710 56545,30700 v1(56545,30220) ; v1(56700,30200) 56810,30200 56825,30215 U5.12
  Bottom Layer w11.81: v1(55355,30835) v1(55355,30920) ; v1(56545,30220) 56565,30200 v1(56700,30200)
"U6 TX": U0.129 U5.11 | length 2784.3
  Top Layer w11.81: U0.129 55203.39,31301.61 55400,31105 v1(55400,30920) ; v1(55400,30835) 55490,30745 56570,30745 56580,30735 v1(56580,30250) ; v1(56675,30235) 56760,30235 56775,30250 U5.11
  Bottom Layer w11.81: v1(55400,30835) v1(55400,30920) ; v1(56580,30250) 56595,30235 v1(56675,30235)
"USB DM": "USB HOST.2" U0.136 | length 2755.6
  Top Layer w11.81: U0.136 54895.36,31439.41 54855.32,31479.46 54855.32,31605.5 55129.81,31880 v1(55640,31880) ; v1(55850,31880) 57115,31880 57135,31860 57135,31790 57102.9,31757.9 57090,31757.9
  Bottom Layer w11.81: v1(55640,31880) v1(55850,31880)
"USB DP": "USB HOST.3" U0.137 | length 2502
  Top Layer w11.81: U0.137 54900.87,31459.09 54875,31484.96 54875,31600 55110,31835 v1(55640,31835) ; v1(55850,31835) 57088.4,31835 57090,31836.6
  Bottom Layer w11.81: v1(55640,31835) v1(55850,31835)
"USB PWR": R21.2 U0.1 | length 2071.4
  Top Layer w11.81: U0.1 v1(54861.5,31740) ; v1(55005,31550) 55015,31540 56540,31540 56577.56,31502.44 R21.2
  Bottom Layer w11.81: v1(54861.5,31740) 54873.28,31751.78 54988.22,31751.78 55005,31735 v1(55005,31550)
VCC3.3: BUZZER.1 C3.1 C4.1 C5.1 C6.1 C7.1 C8.1 C9.1 C10.1 C11.1 C12.1 C13.1 C14.1 C19.2 C35.1 C36.1 C37.1 C50.1 C51.2 D4.1 P3.1 P8.1 P9.1 R1.1 R4.2 R7.1 R9.2 R12.1 R15.1 R40.2 U0.6 U0.17 U0.30 U0.39 U0.52 U0.62 U0.72 U0.84 U0.95 U0.108 U0.121 U0.131 U0.144 U4.2 U5.16 U6.8 U7.8 U9.23 | length 23647.4
  Top Layer w11.81: P8.1 53834.31,31826.81 v1(53835,31827.5) ; R12.1 53314.17,30850.83 v1(53315,30850) ; C36.1 C36.1@53443.47,30879.65 ; U6.8 C36.1@53443.47,30879.65 ; v1(53520,30880) 53443.82,30880 C36.1@53443.47,30879.65 ; C5.1@53677.56,31557.52 53740,31557.52 ; v1(53740,31590) 53740,31557.52 ; v1(53755,29900) 53755,29972.68 R15.1 ; v1(53835,30790) 53895,30790 53905,30800 53905,30852.59 C8.1 53967.8,30852.8 54022.91,30907.91 U0.72 ; v1(53835,31155) 53905,31155 53914.65,31145.35 C7.1 U0.62 ; v1(53835,31355) 53905,31355 53914.64,31345.36 C6.1 U0.52 ; U7.8 53859.18,30205 v1(53915,30205) C37.1 ; U0.39 53740,31557.52 ; U0.30 54290.63,31817.36 C4.1 54351.14,31831.14 54360,31840 v1(54360,31860) ; U0.84 C9.1 54422.99,30652.01 54435,30640 v1(54435,30525) ; U0.17 C3.1 54609.17,31829.17 54620,31840 v1(54620,31860) ; v1(54560,30525) 54560,30640 54570,30650 C10.1 54605.59,30650.59 U0.95 ; P3.1 54646.4,29625 54687.84,29583.57 54948.57,29583.57 54989.88,29624.88 R9.2 55214.88,29624.88 55230,29640 D4.1 55230,29930 55245,29945 v1(55305,29945) ; v1(54655,31860) 54655,31841.14 54665,31831.14 C19.2 U0.6 ; U0.108 C11.1 54939.96,30650.04 v1(54950,30640) ; U0.121 55160.71,31144.13 C12.1 55162.68,31112.32 55170,31105 v1(55305,31105) ; U0.131 C13.1 55164.65,31384.65 55170,31390 v1(55305,31390) ; U0.144 54991.89,31596.89 55115,31720 55161.78,31720 C14.1 55164.65,31575.35 R1.1@55165,31575 ; R1.1 R1.1@55165,31575 ; v1(55305,31575) R1.1@55165,31575 ; v1(55625,30040) 55703.98,30040 U9.23 ; R7.1 55946.14,30958.86 55955,30950 56030,30950 56040,30960 v1(56040,30980) ; R40.2 v1(56470,30350) ; R4.2 v1(56755,30135) 56965,30135 C35.1 U5.16
  Top Layer w23.62: C14.1 55165,31723.22 v1(55165,31775) ; v1(55165,32000) 55271.1,32000 C50.1 C51.2 55850,32385 55870,32405 55870,32530 55850,32550 v1(55845,32550) U4.2
  Bottom Layer w11.81: v1(53315,30850) 53835,30850 ; v1(53520,30880) 53835,30880 ; v1(53740,31590) 53790,31640 53835,31640 ; v1(53755,29900) 53755,29895.2 53755.2,29895 53910,29895 53915,29900 v1(53915,30205) 53915,30525 ; 54950,30515 v1(54950,30640) ; 55305,29880 55320,29865 55595,29865 55610,29880 55610,30025 v1(55625,30040) ; v1(55845,32550) 55845,34110 55890,34155 P9.1 ; 56470,30430 56740,30430 56755,30415 v1(56755,30135) ; 56470,30925 56690,30925 56725,30960 56725,31180.74 BUZZER.1
  Bottom Layer w23.62: 53835,30880 53835,30850 v1(53835,30790) 53835,30540 53850,30525 53915,30525 v1(54435,30525) v1(54560,30525) 55305,30525 ; 53835,30890 v1(53835,31155) v1(53835,31355) 53835,31640 v1(53835,31827.5) 53835,31830 53865,31860 v1(54360,31860) v1(54620,31860) v1(54655,31860) 54910,31860 ; v1(55165,31775) v1(55165,32000) ; 55305,29880 v1(55305,29945) 55305,30525 ; 55305,30980 v1(56040,30980) 56450,30980 56470,30960 56470,30925 56470,30430 v1(56470,30350) ; v1(55560,31985) 55305,31730 v1(55305,31575) v1(55305,31390) v1(55305,31105) 55305,30525
VCC5: C28.1 C43.1 C49.2 D1.2 D2.2 K1.3 K2.3 L1.2 P1.3 P2.3 P5.4 P6.1 Q1.2 R20.2 R50.2 U3.4 U4.3 U8.3 | length 9350.9
  Top Layer w11.81: K2.3 K2.3@53740.98,32790.98 ; U8.3 v1(54525,30115) C28.1 ; D1.2 54758.62,32533.62 54880,32655 54880,32710 ; 54825,32856.37 54825,32860 ; v1(56315,31640) R20.2 56484.88,31759.88 56505,31780 56790,31780 56805,31765 56805,31540 56825.63,31519.37 Q1.2 ; C43.1 C43.1@56700,33008.9
  Top Layer w23.62: v1(53480,32380) 53605,32380 D2.2 53610,32664.29 K2.3 ; K2.3@53740.98,32790.98 53810,32860 54825,32860 ; 54825,32856.37 K1.3 54890.39,32710.39 ; R50.2 55777,32768 U4.3 ; U3.4 56608.07,32613.07 56700,32705 C49.2 C43.1@56700,33008.9
  Bottom Layer w11.81: P2.3@53180.79,31380.35 P2.3 ; P5.4@53714.09,29625 P5.4 53800,29709.8 54504.8,29709.8 54525,29730 v1(54525,30115) ; v1(56285,31915) 56285,31670 v1(56315,31640)
  Bottom Layer w23.62: P6.1 53108.27,30606.73 ; P1.3 53110,31380.35 ; P2.3@53180.79,31380.35 53110,31380.35 ; P2.3@53185,31381.93 53185,32350 53215,32380 v1(53480,32380) ; P5.4@53714.09,29625 53145,29625 53110,29660 53110,31380.35
pads on no net: R2.1 RESET.2 RESET.4 U0.2 U0.3 U0.4 U0.5 U0.7 U0.8 U0.9 U0.10 U0.11 U0.12 U0.13 U0.14 U0.15 U0.18 U0.21 U0.27 U0.28 U0.29 U0.41 U0.43 U0.44 U0.45 U0.47 U0.48 U0.49 U0.50 U0.53 U0.54 U0.55 U0.56 U0.57 U0.58 U0.59 U0.60 U0.63 U0.64 U0.65 U0.66 U0.67 U0.68 U0.76 U0.77 U0.78 U0.79 U0.80 U0.81 U0.82 U0.85 U0.86 U0.87 U0.88 U0.89 U0.90 U0.91 U0.92 U0.93 U0.96 U0.97 U0.98 U0.99 U0.100 U0.103 U0.104 U0.110 U0.111 U0.112 U0.114 U0.115 U0.117 U0.118 U0.119 U0.122 U0.123 U0.125 U0.126 U0.127 U0.128 U0.132 U0.133 U0.135 U0.138 U0.141 U0.142 U2.2 U2.3 U2.4 U2.5 U2.6 U2.7 U2.14 U2.15 U2.16 U2.17 U2.19 U2.21 U2.22 U3.6 U4.4 U5.7 U5.8 U5.9 U5.10 U8.5 U9.1 U9.2 U9.4 U9.5 U9.6 U9.7 U9.8 U9.9 U9.14 U9.15 U9.16 U9.17 U9.18 U9.19 显示屏接口.1 显示屏接口.4 显示屏接口.6 显示屏接口.7 显示屏接口.8 显示屏接口.9

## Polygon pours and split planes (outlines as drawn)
GND on Bottom Layer "Top Layer-No Net" (solid, remove dead copper, pour order 0): 52965,34765 52970,34770 57815,34770 57815,29560 52970,29560 52970,34765 52975,34770
GND on Top Layer "Top Layer-No Net" (solid, remove dead copper, pour order 2): 52970,34770 57815,34770 57815,29560 52970,29560 52970,34770

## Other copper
Top Layer:
  rectangle net GND: 55610.29,31200 55635,31212.12
  rectangle net GND: 55630,31125 55735,31210
  rectangle net NetK1_2: 54970,33320 55110,34205
  rectangle net NetK1_5: 54270,33220 54410,33730
  rectangle net VCC5: 56160,32765 56700,32790
  rectangle net VCC5: 55770,32760 56075,32790
  rectangle: 55590,32415 55720,32670
  rectangle net VCC5: 55895,31980 55935,32780
  rectangle net VCC5: 55895,31965 56305,32000
  rectangle net VCC5: 56270,31905 56305,31970
  rectangle net VCC5: 54870,32700 55785,32725
  rectangle net VCC3.3: 55545,31975 55570,32395
  rectangle net NetK2_5: 53110,33235 53290,34300
  rectangle net NetK2_2: 53490,33320 53665,34300
  rectangle net NetK2_2: 53495,33320 53970,33490
  rectangle net NetK1_2: 54270,34140 55110,34290
  rectangle net NetK1_5: 53870,33615 54030,34300
  rectangle net NetK1_5: 53870,33610 54410,33740
  pour cut-out: 54385,30050 54385,30025 54425,30025 54430,30030 54420,30030 54420,30040 54420,30050
  pour cut-out: 55585,32700 55585.41,32699.59 55585.41,32674.59 55710.62,32674.59 55720,32670 55720,32676.49 55720,32670 55730.55,32668.21 55753.2,32668.2 55758.84,32668.2 55758.84,32693.51 55757.35,32695 55580,32695
  pour cut-out: 55040.04,31530 55085.04,31485 55415,31485 55415,31520 55405,31530
  pour cut-out: 53399.51,31080 53478.15,31080 53492.97,30962.48 53488.54,30958.05 53481.79,30964.8 53397.07,30964.8
  pour cut-out: 53616.34,30958.05 53617.39,30959.1 53617.39,31123.11 53711.89,31123.11 53715,31120 53715,30955 53619.4,30955
  pour cut-out: 53690,31510 54100,31510 54110,31520 54100,31530 54100,31735 53698.19,31735 53690,31726.81
  pour cut-out: 55114.8,31882.16 55120,31876.96 55120,31835 55614.55,31835 55633.05,31853.5 55633.05,31876.95 55625,31885 55622.16,31882.16
  pour cut-out: 55120,31915 55690,31915 55735,31870 55720,31855 55720,31800 55610,31800 55540,31870 55139.81,31870 55120,31889.81
  pour cut-out: 56637.14,30351.07 56637.14,30212.84 56950,30212.84 56950,30355 56641.07,30355
  pour cut-out: 56637.14,30482.88 56639.26,30485 57070,30485 57070,30580 57055,30595 56635,30595 56635,30485.02
  pour cut-out: 56505,32640 56850,32640 56850,32495 56835,32480 56495,32480 56495,32630 56500,32635
  pour cut-out: 57783.28,33940 57770,33940 57720,33990 57720,34046.57 57783.28,33983.28
  pour cut-out: 55590,30210 55590,30000 55595.98,29994.02 55664.84,29994.02 55664.84,30210
  pour cut-out: 54500,31915 54525,31915 54535,31905 54535,31705 54515,31705 54500,31720
  pour cut-out: 55695,31935 55770,31935 55785,31920 55780,31915 55780,31770 55745,31770 55695,31820
  pour cut-out: 55833.22,31873.05 55833.22,31841.95 55840.17,31835 57070,31835 57070,31870 57073.05,31873.05
  pour cut-out: 55801.63,31905 55843.16,31905 55916.52,31831.64 55916.52,31807.85 55814.35,31807.85 55801.84,31820.35 55801.84,31904.69
  pour cut-out: 55555,31835 55555,31765 55555,31767.99 55570,31760 55570,31830 55570,31835
  pour cut-out: 54485,32055 54485,32000.58 54482.47,31998.05 54485.52,31995 54860,31995 54860,32055
  pour cut-out: 55205,30840 55255,30840 55260,30835 55260,30195 55270,30195 55305,30160 55315,30170 55407.56,30170 55407.56,30137.56 55400,30130 55225,30130 55225,30140 55205,30160
  pour cut-out: 55374.19,30193.72 55385.81,30193.72 55385.81,30170 55374.19,30170
  pour cut-out: 56557.24,30247.73 56557.09,30231.64 56561.78,30226.95 56568.14,30233.31 56572.92,30233.31 56567.16,30237.16 56562.41,30247.73
  pour cut-out: 55760.35,30788.79 55760.35,30745.35 55760,30745 55761.42,30743.58 56588.58,30743.58 56588.58,30246.42 56595,30240 56598.05,30243.05 56612.86,30243.05 56612.86,30769.97 56594.97,30787.86 55765,30787.86
  pour cut-out: 54965,31510 54965,31355 54975,31345 55235,31345 55235,31355 55305,31425 55440,31425 55440,31455 55385,31510
  pour cut-out: 54070,31430 54070,31495 54066.54,31498.46 53448.46,31498.46 53275,31325 53190,31325 53190,31291.93 53200,31281.93 53331.93,31281.93 53480,31430
  pour cut-out: 53695,30475 53855,30475 53865,30465 53865,30375 53703.4,30375 53695.28,30383.12 53695.28,30474.72
  pour cut-out: 53735,30255 53880,30255 53880,30160 53735,30160
  pour cut-out: 53727.14,29949.54 53729.55,29947.13 53851.29,29947.13 53851.29,30038.62 53830,30059.91 53830,30160 53757.7,30160 53757.81,30030 53732.01,30030 53727.14,30025.13
  pour cut-out: 54160,30030 54260,30030 54260,30180 54255,30190 54160,30190
  pour cut-out: 54255,30100 54275,30100 54305,30070 54305,29855 54430,29730 54430,29635 54330,29635 54330,29750 54215,29865 54215,29890 54260,29890 54270,29900 54255,29902.14 54255,29915
  pour cut-out: 54380,30185 54480,30185 54480,30080 54377.31,30080
  pour cut-out: 54970,31195 55175,31195 55190,31195 55190,31180 55190,30887.81 54989.3,30887.81 54969.2,30907.91 54970,30908.72

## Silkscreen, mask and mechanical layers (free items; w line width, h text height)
Top Overlay:
  text "4G接口" at 57455,33695 h78.74
  text "串口调试" at 53125,31810 h78.74 r270
  text "霍尔传感器" at 53265,31520 h78.74 r270
  text "温湿度传感器" at 53010,30515 h78.74 r270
